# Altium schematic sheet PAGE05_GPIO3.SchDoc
size 381 x 381 mm; SheetNumber: 6; SheetTotal: 28
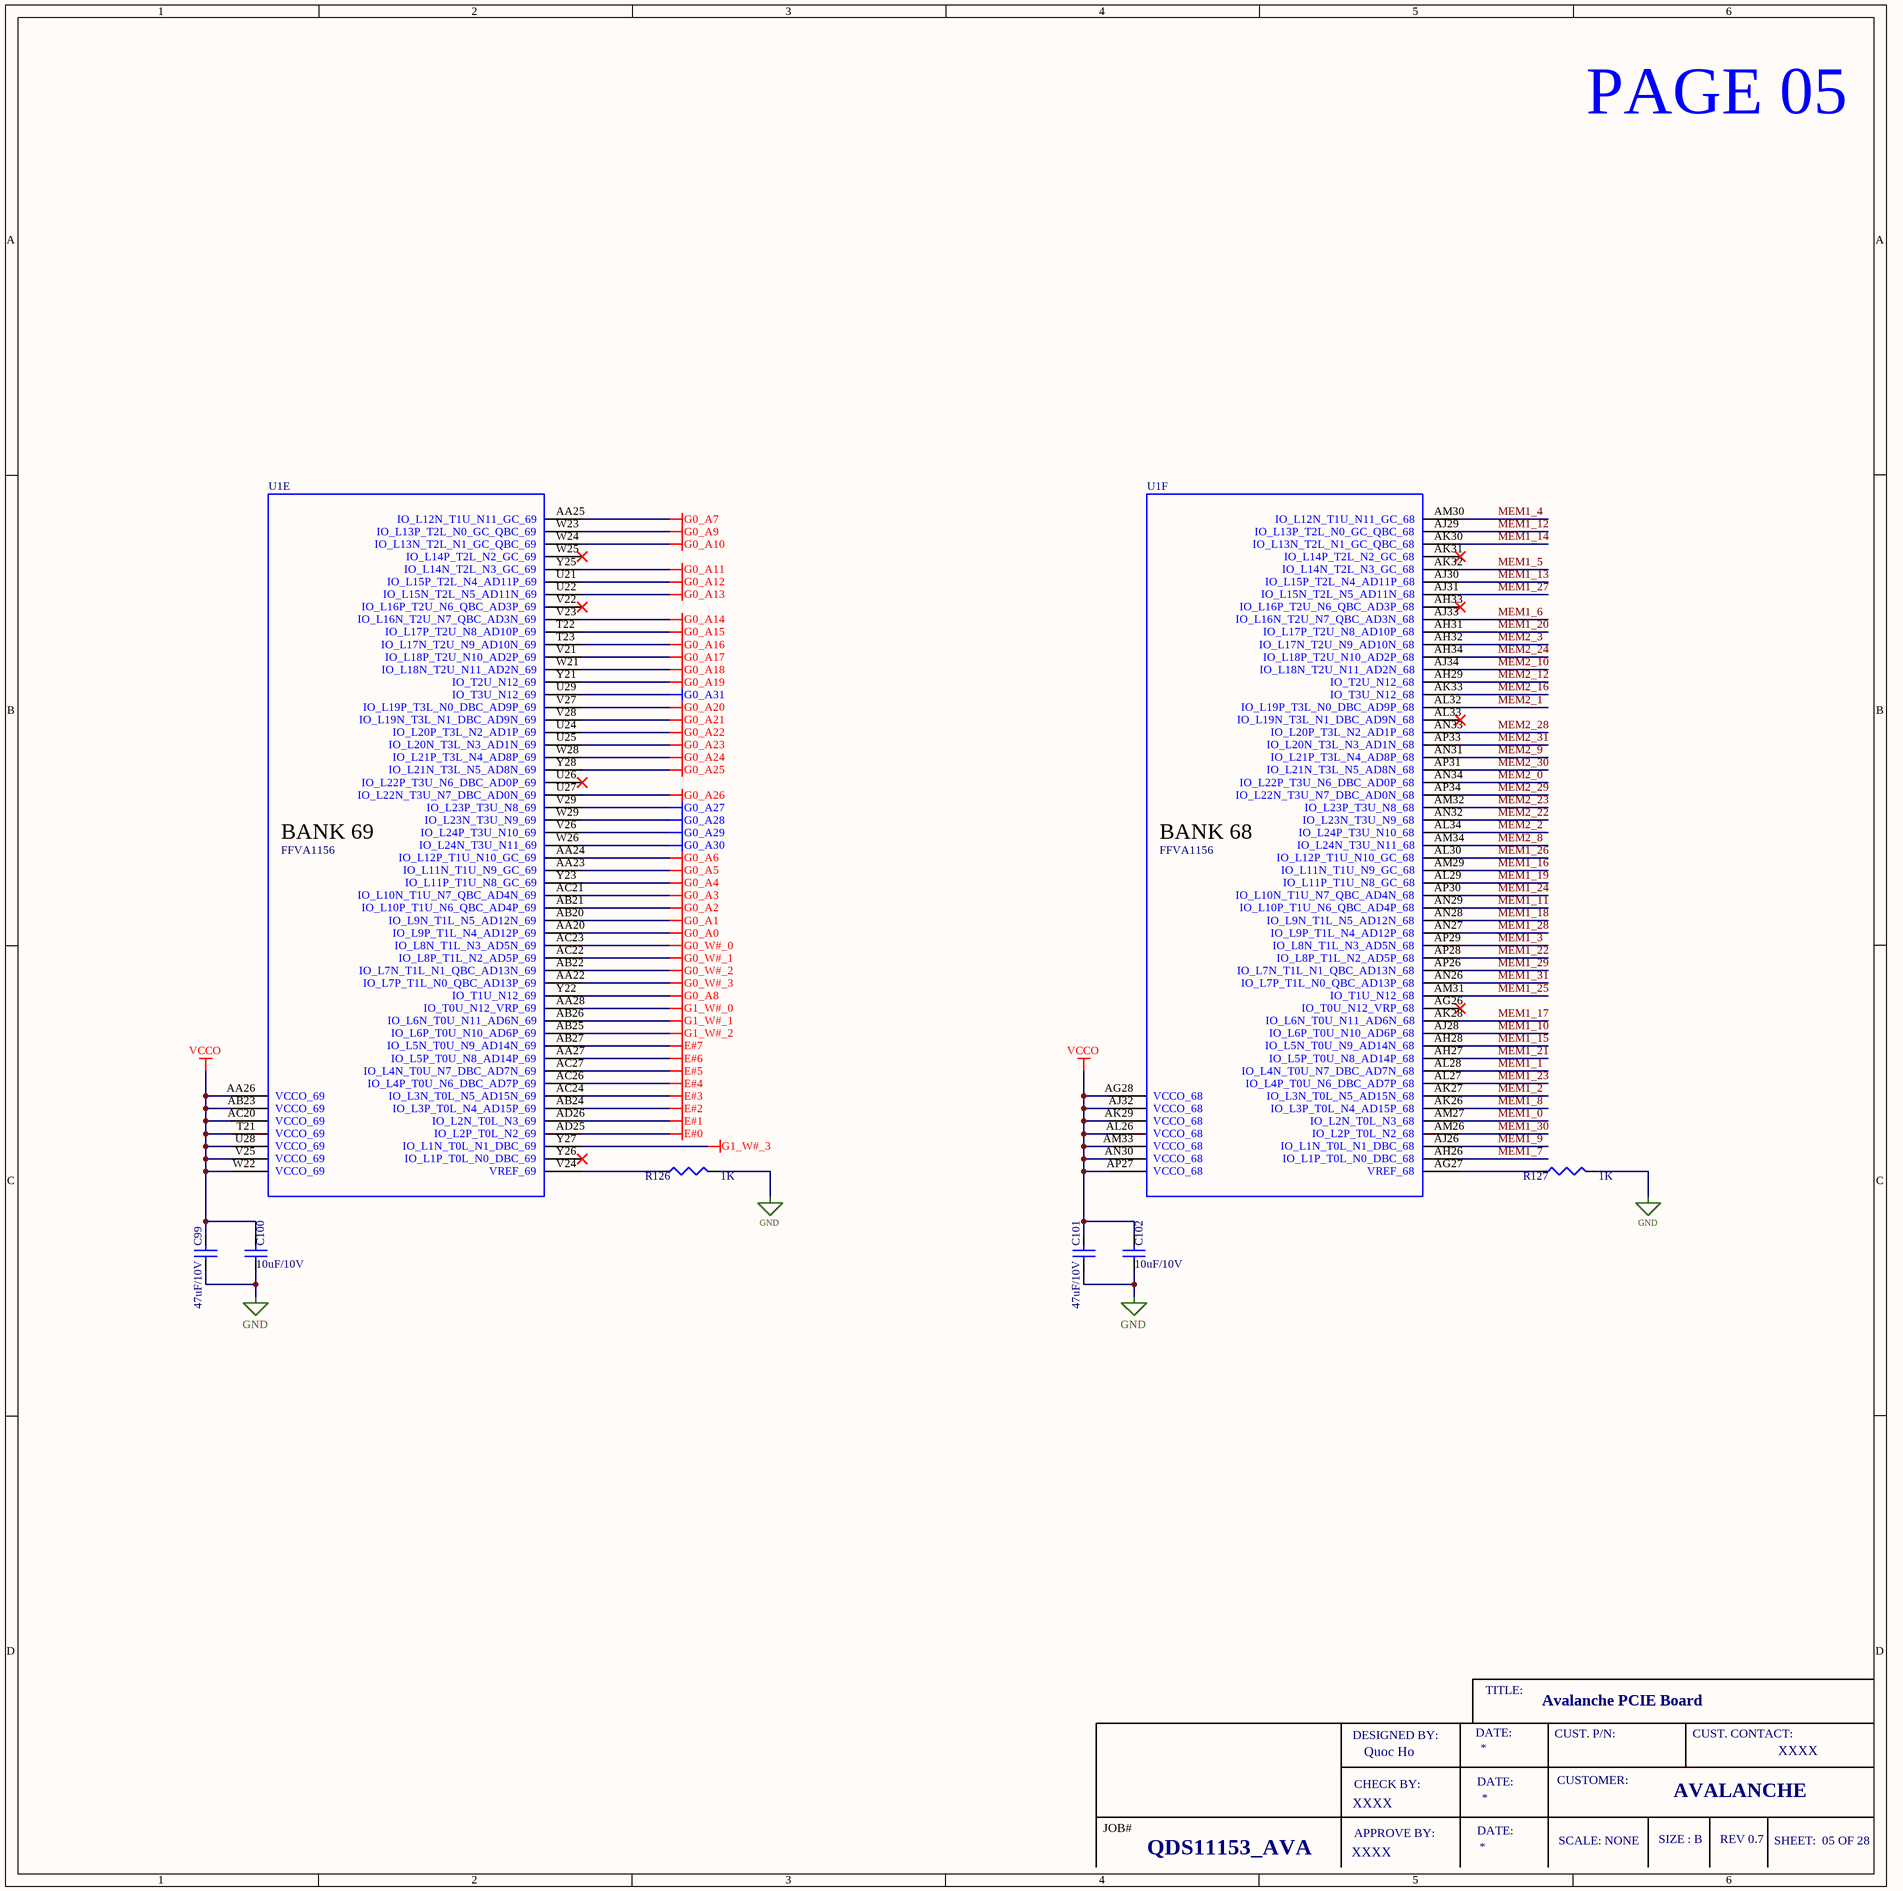
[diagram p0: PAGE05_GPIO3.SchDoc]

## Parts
C99  47uF/10V  [CN_0805]
C100  10uF/10V  [CN_0402]
C101  47uF/10V  [CN_0805]
C102  10uF/10V  [CN_0402]
R126  1K  [RN_0402]
R127  1K  [RN_0402]
U1  FFVA1156  [FFVA1156]  (parts E,F of 25)

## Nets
E#0: U1.AD25(IO_L2P_T0L_N2_69)
E#1: U1.AD26(IO_L2N_T0L_N3_69)
E#2: U1.AB24(IO_L3P_T0L_N4_AD15P_69)
E#3: U1.AC24(IO_L3N_T0L_N5_AD15N_69)
E#4: U1.AC26(IO_L4P_T0U_N6_DBC_AD7P_69)
E#5: U1.AC27(IO_L4N_T0U_N7_DBC_AD7N_69)
E#6: U1.AA27(IO_L5P_T0U_N8_AD14P_69)
E#7: U1.AB27(IO_L5N_T0U_N9_AD14N_69)
G0_A0: U1.AA20(IO_L9P_T1L_N4_AD12P_69)
G0_A1: U1.AB20(IO_L9N_T1L_N5_AD12N_69)
G0_A2: U1.AB21(IO_L10P_T1U_N6_QBC_AD4P_69)
G0_A3: U1.AC21(IO_L10N_T1U_N7_QBC_AD4N_69)
G0_A4: U1.Y23(IO_L11P_T1U_N8_GC_69)
G0_A5: U1.AA23(IO_L11N_T1U_N9_GC_69)
G0_A6: U1.AA24(IO_L12P_T1U_N10_GC_69)
G0_A7: U1.AA25(IO_L12N_T1U_N11_GC_69)
G0_A8: U1.Y22(IO_T1U_N12_69)
G0_A9: U1.W23(IO_L13P_T2L_N0_GC_QBC_69)
G0_A10: U1.W24(IO_L13N_T2L_N1_GC_QBC_69)
G0_A11: U1.Y25(IO_L14N_T2L_N3_GC_69)
G0_A12: U1.U21(IO_L15P_T2L_N4_AD11P_69)
G0_A13: U1.U22(IO_L15N_T2L_N5_AD11N_69)
G0_A14: U1.V23(IO_L16N_T2U_N7_QBC_AD3N_69)
G0_A15: U1.T22(IO_L17P_T2U_N8_AD10P_69)
G0_A16: U1.T23(IO_L17N_T2U_N9_AD10N_69)
G0_A17: U1.V21(IO_L18P_T2U_N10_AD2P_69)
G0_A18: U1.W21(IO_L18N_T2U_N11_AD2N_69)
G0_A19: U1.Y21(IO_T2U_N12_69)
G0_A20: U1.V27(IO_L19P_T3L_N0_DBC_AD9P_69)
G0_A21: U1.V28(IO_L19N_T3L_N1_DBC_AD9N_69)
G0_A22: U1.U24(IO_L20P_T3L_N2_AD1P_69)
G0_A23: U1.U25(IO_L20N_T3L_N3_AD1N_69)
G0_A24: U1.W28(IO_L21P_T3L_N4_AD8P_69)
G0_A25: U1.Y28(IO_L21N_T3L_N5_AD8N_69)
G0_A26: U1.U27(IO_L22N_T3U_N7_DBC_AD0N_69)
G0_A27: U1.V29(IO_L23P_T3U_N8_69)
G0_A28: U1.W29(IO_L23N_T3U_N9_69)
G0_A29: U1.V26(IO_L24P_T3U_N10_69)
G0_A30: U1.W26(IO_L24N_T3U_N11_69)
G0_A31: U1.U29(IO_T3U_N12_69)
G0_W#_0: U1.AC23(IO_L8N_T1L_N3_AD5N_69)
G0_W#_1: U1.AC22(IO_L8P_T1L_N2_AD5P_69)
G0_W#_2: U1.AB22(IO_L7N_T1L_N1_QBC_AD13N_69)
G0_W#_3: U1.AA22(IO_L7P_T1L_N0_QBC_AD13P_69)
G1_W#_0: U1.AA28(IO_T0U_N12_VRP_69)
G1_W#_1: U1.AB26(IO_L6N_T0U_N11_AD6N_69)
G1_W#_2: U1.AB25(IO_L6P_T0U_N10_AD6P_69)
G1_W#_3: U1.Y27(IO_L1N_T0L_N1_DBC_69)
GND: C99.1 C100.1 C101.1 C102.1 R126.2 R127.2
VCCO: C99.2 C100.2 C101.2 C102.2 U1.AA26(VCCO_69) U1.AB23(VCCO_69) U1.AC20(VCCO_69) U1.AG28(VCCO_68) U1.AJ32(VCCO_68) U1.AK29(VCCO_68) U1.AL26(VCCO_68) U1.AM33(VCCO_68) U1.AN30(VCCO_68) U1.AP27(VCCO_68) U1.T21(VCCO_69) U1.U28(VCCO_69) U1.V25(VCCO_69) U1.W22(VCCO_69)
MEM1_0: U1.AM27(IO_L2N_T0L_N3_68)
MEM1_1: U1.AL28(IO_L4N_T0U_N7_DBC_AD7N_68)
MEM1_2: U1.AK27(IO_L3N_T0L_N5_AD15N_68)
MEM1_3: U1.AP29(IO_L8N_T1L_N3_AD5N_68)
MEM1_4: U1.AM30(IO_L12N_T1U_N11_GC_68)
MEM1_5: U1.AK32(IO_L14N_T2L_N3_GC_68)
MEM1_6: U1.AJ33(IO_L16N_T2U_N7_QBC_AD3N_68)
MEM1_7: U1.AH26(IO_L1P_T0L_N0_DBC_68)
MEM1_8: U1.AK26(IO_L3P_T0L_N4_AD15P_68)
MEM1_9: U1.AJ26(IO_L1N_T0L_N1_DBC_68)
MEM1_10: U1.AJ28(IO_L6P_T0U_N10_AD6P_68)
MEM1_11: U1.AN29(IO_L10P_T1U_N6_QBC_AD4P_68)
MEM1_12: U1.AJ29(IO_L13P_T2L_N0_GC_QBC_68)
MEM1_13: U1.AJ30(IO_L15P_T2L_N4_AD11P_68)
MEM1_14: U1.AK30(IO_L13N_T2L_N1_GC_QBC_68)
MEM1_15: U1.AH28(IO_L5N_T0U_N9_AD14N_68)
MEM1_16: U1.AM29(IO_L11N_T1U_N9_GC_68)
MEM1_17: U1.AK28(IO_L6N_T0U_N11_AD6N_68)
MEM1_18: U1.AN28(IO_L9N_T1L_N5_AD12N_68)
MEM1_19: U1.AL29(IO_L11P_T1U_N8_GC_68)
MEM1_20: U1.AH31(IO_L17P_T2U_N8_AD10P_68)
MEM1_21: U1.AH27(IO_L5P_T0U_N8_AD14P_68)
MEM1_22: U1.AP28(IO_L8P_T1L_N2_AD5P_68)
MEM1_23: U1.AL27(IO_L4P_T0U_N6_DBC_AD7P_68)
MEM1_24: U1.AP30(IO_L10N_T1U_N7_QBC_AD4N_68)
MEM1_25: U1.AM31(IO_T1U_N12_68)
MEM1_26: U1.AL30(IO_L12P_T1U_N10_GC_68)
MEM1_27: U1.AJ31(IO_L15N_T2L_N5_AD11N_68)
MEM1_28: U1.AN27(IO_L9P_T1L_N4_AD12P_68)
MEM1_29: U1.AP26(IO_L7N_T1L_N1_QBC_AD13N_68)
MEM1_30: U1.AM26(IO_L2P_T0L_N2_68)
MEM1_31: U1.AN26(IO_L7P_T1L_N0_QBC_AD13P_68)
MEM2_0: U1.AN34(IO_L22P_T3U_N6_DBC_AD0P_68)
MEM2_1: U1.AL32(IO_L19P_T3L_N0_DBC_AD9P_68)
MEM2_2: U1.AL34(IO_L24P_T3U_N10_68)
MEM2_3: U1.AH32(IO_L17N_T2U_N9_AD10N_68)
MEM2_8: U1.AM34(IO_L24N_T3U_N11_68)
MEM2_9: U1.AN31(IO_L21P_T3L_N4_AD8P_68)
MEM2_10: U1.AJ34(IO_L18N_T2U_N11_AD2N_68)
MEM2_12: U1.AH29(IO_T2U_N12_68)
MEM2_16: U1.AK33(IO_T3U_N12_68)
MEM2_22: U1.AN32(IO_L23N_T3U_N9_68)
MEM2_23: U1.AM32(IO_L23P_T3U_N8_68)
MEM2_24: U1.AH34(IO_L18P_T2U_N10_AD2P_68)
MEM2_28: U1.AN33(IO_L20P_T3L_N2_AD1P_68)
MEM2_29: U1.AP34(IO_L22N_T3U_N7_DBC_AD0N_68)
MEM2_30: U1.AP31(IO_L21N_T3L_N5_AD8N_68)
MEM2_31: U1.AP33(IO_L20N_T3L_N3_AD1N_68)
NetR126_1: R126.1 U1.V24(VREF_69)
NetR127_1: R127.1 U1.AG27(VREF_68)

Not connected (* = marked no-connect by the designer): U1 AG26(IO_T0U_N12_VRP_68)* AH33(IO_L16P_T2U_N6_QBC_AD3P_68)* AK31(IO_L14P_T2L_N2_GC_68)* AL33(IO_L19N_T3L_N1_DBC_AD9N_68)* U26(IO_L22P_T3U_N6_DBC_AD0P_69)* V22(IO_L16P_T2U_N6_QBC_AD3P_69)* W25(IO_L14P_T2L_N2_GC_69)* Y26(IO_L1P_T0L_N0_DBC_69)*

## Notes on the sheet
- PAGE 05
- (near U1) BANK 69
- (near U1) BANK 68
- TITLE:
- Avalanche PCIE Board
- DESIGNED BY:
- CHECK BY:
- Quoc Ho
- DATE:
- CUST. P/N:
- CUSTOMER:
- CUST. CONTACT:
- XXXX
- JOB#
- APPROVE BY:
- SCALE: NONE
- SIZE : B
- AVALANCHE
- REV 0.7
- SHEET:  05 OF 28
- QDS11153_AVA

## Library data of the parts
C99 C101 = CAP: CAP CER 47UF 10V X5R 0805; Manufacturer: Murata Electronics; Manufacturer Part Number: GRM21BR61A476ME15K
C100 C102 = CAP: CAP CER 10UF 10V X5R 0402; Manufacturer Part Number: GRM155R61A106ME11D; Manufacturer: Murata Electronics
R126 R127 = RES: RES 1K OHM 1% 1/16W 0402; Manufacturer Part Number: RC0402FR-131KL; Manufacturer: YAGEO
U1 = FFVA1156: IC FPGA 516 I/O 1156FCBGA; Manufacturer Part Number: XCKU15P-1FFVA1156E; Manufacturer: AMD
